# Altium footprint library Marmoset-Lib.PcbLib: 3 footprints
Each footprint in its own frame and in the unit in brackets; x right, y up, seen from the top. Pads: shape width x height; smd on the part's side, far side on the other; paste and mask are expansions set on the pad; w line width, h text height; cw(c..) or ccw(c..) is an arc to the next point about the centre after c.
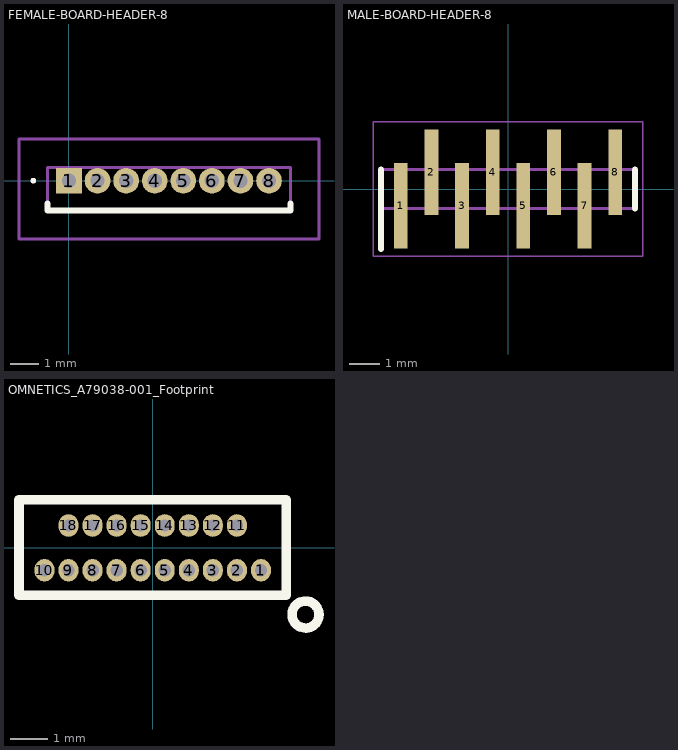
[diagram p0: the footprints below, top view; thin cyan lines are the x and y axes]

## FEMALE-BOARD-HEADER-8 [mm]
pads (8):
  rect 0.9x0.9 hole 0.5: 1(0,0)
  round 0.9 hole 0.5: 2(1,0) 3(2,0) 4(3,0) 5(4,0) 6(5,0) 7(6,0) 8(7,0)
Top Overlay:
  lines w0.1: -1.3,0 ccw(c-1.25,0) -1.2,0 ccw(c-1.25,0) -1.3,0
  lines w0.2: -0.75,-0.8 -0.75,-1.04 7.75,-1.04 7.75,-0.8
Mechanical 13:
  lines w0.1: -0.75,-1.04 -0.75,0.46 7.75,0.46 7.75,-1.04 -0.75,-1.04
Mechanical 15:
  lines w0.1: -1.75,-2.04 -1.75,1.46 8.75,1.46 8.75,-2.04 -1.75,-2.04
3D body "BC065-08-A-L-D.STEP": height 2.1, standoff -1.8, extent -0.75,-1 7.75,0.5

## MALE-BOARD-HEADER-8 [mm]
pads (8):
  rect 0.45x2.8 smd: 1(-3.5,-0.55) 2(-2.5,0.55) 3(-1.5,-0.55) 4(-0.5,0.55) 5(0.5,-0.55) 6(1.5,0.55) 7(2.5,-0.55) 8(3.5,0.55)
Top Overlay:
  lines w0.2: -4.15,-1.95 -4.15,0.635 ; 4.15,-0.635 4.15,0.635
Mechanical 13:
  lines w0.1: -4.15,-0.635 4.15,-0.635 4.15,0.635 -4.15,0.635 -4.15,-0.635
Mechanical 15:
  lines w0.05: -4.4,-2.2 4.4,-2.2 4.4,2.2 -4.4,2.2 -4.4,-2.2
3D body "BC032-08-A-2-0200-0200-L-B.STEP": height 4, standoff 0, extent -4,-1.25 4,1.25

## OMNETICS_A79038-001_Footprint [mm]
pads (18):
  oval 0.53x0.6 / inner round 0.53 / far side oval 0.53x0.6 hole 0.33 paste-2539.97 mask+0: 1(2.88,-0.6) 2(2.24,-0.6) 3(1.6,-0.6) 4(0.96,-0.6) 5(0.32,-0.6) 6(-0.32,-0.6) 7(-0.96,-0.6) 8(-1.6,-0.6) 9(-2.24,-0.6) 10(-2.88,-0.6) 11(2.24,0.591) 12(1.6,0.591) 13(0.96,0.591) 14(0.32,0.591) 15(-0.32,0.591) 16(-0.96,0.591) 17(-1.6,0.591) 18(-2.24,0.591)
Top Overlay:
  circle w0.254: c4.064,-1.778 r0.359
  lines w0.254: -3.556,-1.27 -3.556,1.27 3.556,1.27 3.556,-1.27 -3.556,-1.27
3D body "A79038-001.STEP": height 4.61, standoff -2.32, extent -3.365,-0.889 3.365,0.902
